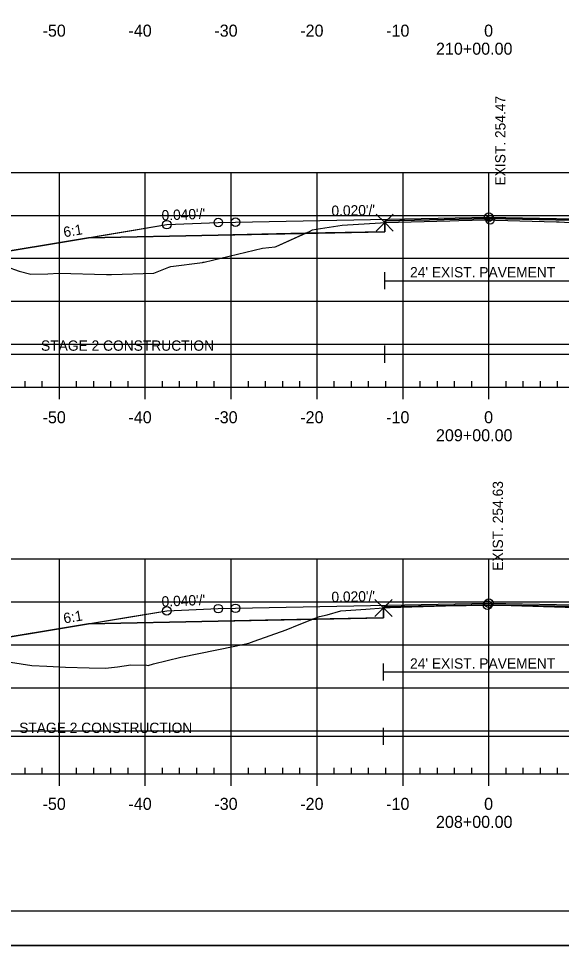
# Model space of a CAD drawing. Extents: x 1365647 to 1367999, y 387113 to 400173.
# Drawn here: x 1365839.3 to 1365902.5, y 390359.5 to 390467.4 of the extents above; entities that cross this region are included whole.
import ezdxf

# ---------------------------------------------------------------- set-up
doc = ezdxf.new("R2010")
doc.units = 0
for name, color, linetype in [('R_Alt Surface', 7, 'Continuous'), ('R_Axis', 7, 'Continuous'), ('R_Axis Annot', 7, 'Continuous'), ('R_Border', 7, 'Continuous'), ('R_Contours', 7, 'Continuous'), ('R_Exist Surface', 7, 'Continuous'), ('R_Fin Surface', 7, 'Continuous'), ('R_Fin Surface Annot', 7, 'Continuous'), ('R_Grid', 7, 'Continuous'), ('R_No Plot', 7, 'Continuous'), ('R_Water', 7, 'Continuous'), ('R_Xsect Elev', 7, 'Continuous')]:
    doc.layers.add(name, color=color, linetype=linetype)

msp = doc.modelspace()

# ---------------------------------------------------------------- linework, layer by layer
at = {"layer": 'R_Alt Surface'}
for points in [[(1365847.47, 390441.85), (1365862.59, 390442.16), (1365881.96, 390442.54), (1365881.96, 390443.83), (1365894.09, 390444.07), (1365905.79, 390443.84), (1365905.79, 390442.55), (1365925.59, 390442.16), (1365940.72, 390441.85)], [(1365847.47, 390396.91), (1365862.59, 390397.21), (1365881.82, 390397.59), (1365881.82, 390398.88), (1365894.09, 390399.13), (1365905.66, 390398.89), (1365905.66, 390397.61), (1365925.59, 390397.21), (1365940.72, 390396.91)]]:
    msp.add_lwpolyline(points, dxfattribs=at)
at = {"layer": 'R_Axis'}
for p, q in [((1365840.09, 390424.45), (1365840.09, 390425.15)), ((1365842.09, 390424.45), (1365842.09, 390425.15)), ((1365846.09, 390424.45), (1365846.09, 390425.15)), ((1365848.09, 390424.45), (1365848.09, 390425.15)), ((1365850.09, 390424.45), (1365850.09, 390425.15)), ((1365852.09, 390424.45), (1365852.09, 390425.15)), ((1365856.09, 390424.45), (1365856.09, 390425.15)), ((1365858.09, 390424.45), (1365858.09, 390425.15)), ((1365860.09, 390424.45), (1365860.09, 390425.15)), ((1365862.09, 390424.45), (1365862.09, 390425.15)), ((1365866.09, 390424.45), (1365866.09, 390425.15)), ((1365868.09, 390424.45), (1365868.09, 390425.15)), ((1365870.09, 390424.45), (1365870.09, 390425.15)), ((1365872.09, 390424.45), (1365872.09, 390425.15)), ((1365876.09, 390424.45), (1365876.09, 390425.15)), ((1365878.09, 390424.45), (1365878.09, 390425.15)), ((1365880.09, 390424.45), (1365880.09, 390425.15)), ((1365882.09, 390424.45), (1365882.09, 390425.15)), ((1365886.09, 390424.45), (1365886.09, 390425.15)), ((1365888.09, 390424.45), (1365888.09, 390425.15)), ((1365890.09, 390424.45), (1365890.09, 390425.15)), ((1365892.09, 390424.45), (1365892.09, 390425.15)), ((1365896.09, 390424.45), (1365896.09, 390425.15)), ((1365898.09, 390424.45), (1365898.09, 390425.15)), ((1365900.09, 390424.45), (1365900.09, 390425.15)), ((1365902.09, 390424.45), (1365902.09, 390425.15)), ((1365749.09, 390424.45), (1366039.09, 390424.45)), ((1365844.09, 390423.05), (1365844.09, 390424.45)), ((1365854.09, 390423.05), (1365854.09, 390424.45)), ((1365864.09, 390423.05), (1365864.09, 390424.45)), ((1365874.09, 390423.05), (1365874.09, 390424.45)), ((1365884.09, 390423.05), (1365884.09, 390424.45)), ((1365894.09, 390423.05), (1365894.09, 390424.45)), ((1365840.09, 390379.45), (1365840.09, 390380.15)), ((1365842.09, 390379.45), (1365842.09, 390380.15)), ((1365846.09, 390379.45), (1365846.09, 390380.15)), ((1365848.09, 390379.45), (1365848.09, 390380.15)), ((1365850.09, 390379.45), (1365850.09, 390380.15)), ((1365852.09, 390379.45), (1365852.09, 390380.15)), ((1365856.09, 390379.45), (1365856.09, 390380.15)), ((1365858.09, 390379.45), (1365858.09, 390380.15)), ((1365860.09, 390379.45), (1365860.09, 390380.15)), ((1365862.09, 390379.45), (1365862.09, 390380.15)), ((1365866.09, 390379.45), (1365866.09, 390380.15)), ((1365868.09, 390379.45), (1365868.09, 390380.15)), ((1365870.09, 390379.45), (1365870.09, 390380.15)), ((1365872.09, 390379.45), (1365872.09, 390380.15)), ((1365876.09, 390379.45), (1365876.09, 390380.15)), ((1365878.09, 390379.45), (1365878.09, 390380.15)), ((1365880.09, 390379.45), (1365880.09, 390380.15)), ((1365882.09, 390379.45), (1365882.09, 390380.15)), ((1365886.09, 390379.45), (1365886.09, 390380.15)), ((1365888.09, 390379.45), (1365888.09, 390380.15)), ((1365890.09, 390379.45), (1365890.09, 390380.15)), ((1365892.09, 390379.45), (1365892.09, 390380.15)), ((1365896.09, 390379.45), (1365896.09, 390380.15)), ((1365898.09, 390379.45), (1365898.09, 390380.15)), ((1365900.09, 390379.45), (1365900.09, 390380.15)), ((1365902.09, 390379.45), (1365902.09, 390380.15)), ((1365749.09, 390379.45), (1366039.09, 390379.45)), ((1365844.09, 390378.05), (1365844.09, 390379.45)), ((1365854.09, 390378.05), (1365854.09, 390379.45)), ((1365864.09, 390378.05), (1365864.09, 390379.45)), ((1365874.09, 390378.05), (1365874.09, 390379.45)), ((1365884.09, 390378.05), (1365884.09, 390379.45)), ((1365894.09, 390378.05), (1365894.09, 390379.45))]:
    msp.add_line(p, q, dxfattribs=at)
at = {"layer": 'R_Border'}
msp.add_line((1366052.27, 390363.45), (1365736.09, 390363.45), dxfattribs=at)
at = {"layer": 'R_Contours'}
for points in [[(1365872.75, 390442.36), (1365873.19, 390442.56), (1365873.55, 390442.75), (1365873.99, 390442.83), (1365877, 390443.32), (1365881.48, 390443.57), (1365881.96, 390443.6), (1365881.96, 390442.54)], [(1365881.96, 390443.6), (1365882.07, 390443.61), (1365889.54, 390443.83), (1365890.57, 390443.86), (1365893.74, 390443.92), (1365894.07, 390443.92), (1365894.22, 390443.92), (1365894.25, 390443.92), (1365894.87, 390443.9), (1365901.94, 390443.7), (1365902.25, 390443.69), (1365905.37, 390443.52), (1365905.79, 390443.5), (1365905.79, 390443.84), (1365894.09, 390444.07), (1365881.96, 390443.83)], [(1365832.89, 390439.14), (1365833.73, 390439.05), (1365835.07, 390438.94), (1365837.89, 390438.49), (1365839.41, 390437.96), (1365840.78, 390437.6), (1365842.75, 390437.66), (1365844.02, 390437.71), (1365849.58, 390437.55), (1365849.9, 390437.55), (1365850.15, 390437.55), (1365855.08, 390437.72), (1365856.82, 390438.41), (1365857.08, 390438.5), (1365860.75, 390438.98), (1365860.82, 390438.99), (1365860.93, 390439.01), (1365867.74, 390440.64), (1365869.19, 390440.8), (1365869.32, 390440.83), (1365872.75, 390442.36), (1365862.59, 390442.16), (1365847.47, 390441.85), (1365834.59, 390439.71)], [(1365873.55, 390397.43), (1365874.36, 390397.74), (1365875.25, 390397.96), (1365876.87, 390398.41), (1365879.78, 390398.6), (1365881.82, 390398.75), (1365881.82, 390397.59)], [(1365881.82, 390398.75), (1365882.38, 390398.79), (1365882.61, 390398.8), (1365883.85, 390398.84), (1365890.3, 390399.02), (1365891.43, 390399.03), (1365893.93, 390399.08), (1365894.26, 390399.09), (1365894.37, 390399.09), (1365895.4, 390399.07), (1365902.95, 390398.84), (1365903.63, 390398.82), (1365904.3, 390398.78), (1365905.66, 390398.71), (1365905.66, 390398.89), (1365894.09, 390399.13), (1365881.82, 390398.88)]]:
    msp.add_lwpolyline(points, close=True, dxfattribs=at)
msp.add_lwpolyline([(1365835.87, 390392.84), (1365840.87, 390392.06), (1365842.61, 390391.99), (1365844.81, 390391.87), (1365847.55, 390391.8), (1365849.47, 390391.75), (1365850.85, 390391.91), (1365852.42, 390392.15), (1365854.26, 390392.09), (1365854.43, 390392.07), (1365855.05, 390392.23), (1365858.23, 390393.01), (1365864.53, 390394.3), (1365866.15, 390394.65), (1365866.76, 390394.87), (1365870.5, 390396.22), (1365872, 390396.83), (1365873.55, 390397.43), (1365862.59, 390397.21), (1365847.47, 390396.91), (1365834.59, 390394.76)], dxfattribs=at)
at = {"layer": 'R_Exist Surface'}
for points in [[(1365837.89, 390438.49), (1365839.41, 390437.96), (1365840.78, 390437.6), (1365842.75, 390437.66), (1365844.02, 390437.71), (1365849.58, 390437.55), (1365849.9, 390437.55), (1365850.15, 390437.55), (1365855.08, 390437.72), (1365856.82, 390438.41), (1365857.08, 390438.5), (1365860.75, 390438.98), (1365860.82, 390438.99), (1365860.93, 390439.01), (1365867.74, 390440.64), (1365869.19, 390440.8), (1365869.32, 390440.83), (1365873.19, 390442.56), (1365873.55, 390442.75), (1365873.99, 390442.83), (1365877, 390443.32), (1365881.48, 390443.57), (1365881.96, 390443.6), (1365882.07, 390443.61), (1365889.54, 390443.83), (1365890.57, 390443.86), (1365893.74, 390443.92), (1365894.07, 390443.92), (1365894.22, 390443.92), (1365894.25, 390443.92), (1365894.87, 390443.9), (1365901.94, 390443.7), (1365902.25, 390443.69), (1365905.37, 390443.52)], [(1365835.87, 390392.84), (1365840.87, 390392.06), (1365842.61, 390391.99), (1365844.81, 390391.87), (1365847.55, 390391.8), (1365849.47, 390391.75), (1365850.85, 390391.91), (1365852.42, 390392.15), (1365854.26, 390392.09), (1365854.43, 390392.07), (1365855.05, 390392.23), (1365858.23, 390393.01), (1365864.53, 390394.3), (1365866.15, 390394.65), (1365866.76, 390394.87), (1365870.5, 390396.22), (1365872, 390396.83), (1365874.36, 390397.74), (1365875.25, 390397.96), (1365876.87, 390398.41), (1365879.78, 390398.6), (1365881.82, 390398.75), (1365882.38, 390398.79), (1365882.61, 390398.8), (1365883.85, 390398.84), (1365890.3, 390399.02), (1365891.43, 390399.03), (1365893.93, 390399.08), (1365894.26, 390399.09), (1365894.37, 390399.09), (1365895.4, 390399.07), (1365902.95, 390398.84)]]:
    msp.add_lwpolyline(points, dxfattribs=at)
at = {"layer": 'R_Fin Surface'}
for points in [[(1365823.17, 390439), (1365827.81, 390437.45), (1365834.59, 390439.71), (1365847.47, 390441.85), (1365856.59, 390443.37), (1365862.59, 390443.61), (1365864.59, 390443.65), (1365894.09, 390444.24), (1365923.59, 390443.65), (1365925.59, 390443.61), (1365931.59, 390443.37), (1365940.72, 390441.85), (1365953.59, 390439.71), (1365961.09, 390437.21), (1365964.15, 390438.23)], [(1365829.91, 390438.15), (1365834.59, 390439.71), (1365856.59, 390443.37), (1365862.59, 390443.61), (1365864.59, 390443.65), (1365894.09, 390444.24), (1365923.59, 390443.65), (1365925.59, 390443.61), (1365931.59, 390443.37), (1365953.59, 390439.71), (1365961.09, 390437.21), (1365964.15, 390438.23)], [(1365832.89, 390439.14), (1365834.59, 390439.71), (1365852.3, 390442.66), (1365856.59, 390443.37), (1365862.59, 390443.61), (1365864.59, 390443.65), (1365894.09, 390444.24), (1365923.59, 390443.65), (1365925.59, 390443.61), (1365931.59, 390443.37), (1365935.89, 390442.66), (1365953.59, 390439.71)], [(1365856.59, 390443.37), (1365862.59, 390443.61), (1365864.59, 390443.65), (1365894.09, 390444.24), (1365923.59, 390443.65), (1365925.59, 390443.61), (1365931.59, 390443.37)], [(1365818.9, 390393.37), (1365824.66, 390391.45), (1365834.59, 390394.76), (1365847.47, 390396.91), (1365856.59, 390398.43), (1365862.59, 390398.67), (1365864.59, 390398.71), (1365894.09, 390399.3), (1365923.59, 390398.71), (1365925.59, 390398.67), (1365931.59, 390398.43), (1365940.72, 390396.91), (1365953.59, 390394.76), (1365962.39, 390391.83), (1365965.77, 390392.95)], [(1365827.66, 390392.45), (1365834.59, 390394.76), (1365856.59, 390398.43), (1365862.59, 390398.67), (1365864.59, 390398.71), (1365894.09, 390399.3), (1365923.59, 390398.71), (1365925.59, 390398.67), (1365931.59, 390398.43), (1365953.59, 390394.76), (1365962.39, 390391.83), (1365965.77, 390392.95)], [(1365829.97, 390393.22), (1365834.59, 390394.76), (1365852.3, 390397.71), (1365856.59, 390398.43), (1365862.59, 390398.67), (1365864.59, 390398.71), (1365894.09, 390399.3), (1365923.59, 390398.71), (1365925.59, 390398.67), (1365931.59, 390398.43), (1365935.89, 390397.71), (1365953.59, 390394.76), (1365959.02, 390392.95)], [(1365856.59, 390398.43), (1365862.59, 390398.67), (1365864.59, 390398.71), (1365894.09, 390399.3), (1365923.59, 390398.71), (1365925.59, 390398.67), (1365931.59, 390398.43)]]:
    msp.add_lwpolyline(points, dxfattribs=at)
at = {"layer": 'R_Grid'}
for p, q in [((1365749.09, 390449.45), (1366039.09, 390449.45)), ((1365844.09, 390424.45), (1365844.09, 390449.45)), ((1365854.09, 390424.45), (1365854.09, 390449.45)), ((1365864.09, 390424.45), (1365864.09, 390449.45)), ((1365874.09, 390424.45), (1365874.09, 390449.45)), ((1365884.09, 390424.45), (1365884.09, 390449.45)), ((1365894.09, 390424.45), (1365894.09, 390449.45)), ((1365749.09, 390444.45), (1366039.09, 390444.45)), ((1365749.09, 390439.45), (1366039.09, 390439.45)), ((1365749.09, 390434.45), (1366039.09, 390434.45)), ((1365749.09, 390429.45), (1366039.09, 390429.45)), ((1365749.09, 390424.45), (1366039.09, 390424.45)), ((1365749.09, 390404.45), (1366039.09, 390404.45)), ((1365844.09, 390379.45), (1365844.09, 390404.45)), ((1365854.09, 390379.45), (1365854.09, 390404.45)), ((1365864.09, 390379.45), (1365864.09, 390404.45)), ((1365874.09, 390379.45), (1365874.09, 390404.45)), ((1365884.09, 390379.45), (1365884.09, 390404.45)), ((1365894.09, 390379.45), (1365894.09, 390404.45)), ((1365749.09, 390399.45), (1366039.09, 390399.45)), ((1365749.09, 390394.45), (1366039.09, 390394.45)), ((1365749.09, 390389.45), (1366039.09, 390389.45)), ((1365749.09, 390384.45), (1366039.09, 390384.45)), ((1365749.09, 390379.45), (1366039.09, 390379.45))]:
    msp.add_line(p, q, dxfattribs=at)
at = {"layer": 'R_No Plot'}
msp.add_line((1365723.69, 390359.47), (1366057.03, 390359.47), dxfattribs=at)
msp.add_lwpolyline([(1365723.69, 390572.8), (1366057.03, 390572.8), (1366057.03, 390359.47), (1365723.69, 390359.47)], close=True, dxfattribs=at)
for points in [[(1365881.96, 390443.6), (1365880.96, 390444.6), (1365881.96, 390443.6), (1365880.96, 390442.6), (1365881.96, 390443.6), (1365882.96, 390442.6), (1365881.96, 390443.6), (1365882.96, 390444.6)], [(1365881.82, 390398.75), (1365880.82, 390399.75), (1365881.82, 390398.75), (1365880.82, 390397.75), (1365881.82, 390398.75), (1365882.82, 390397.75), (1365881.82, 390398.75), (1365882.82, 390399.75)]]:
    msp.add_lwpolyline(points, dxfattribs=at)
for centre in [(1365894.09, 390444.24), (1365894.09, 390444.24), (1365894.09, 390444.24), (1365894.09, 390444.24), (1365894.09, 390444.24), (1365856.59, 390443.37), (1365856.59, 390443.37), (1365856.59, 390443.37), (1365856.59, 390443.37), (1365856.59, 390443.37), (1365862.59, 390443.61), (1365862.59, 390443.61), (1365862.59, 390443.61), (1365862.59, 390443.61), (1365862.59, 390443.61), (1365864.59, 390443.65), (1365864.59, 390443.65), (1365864.59, 390443.65), (1365864.59, 390443.65), (1365864.59, 390443.65), (1365894.22, 390443.92), (1365893.93, 390399.08), (1365894.09, 390399.3), (1365894.09, 390399.3), (1365894.09, 390399.3), (1365894.09, 390399.3), (1365894.09, 390399.3), (1365856.59, 390398.43), (1365856.59, 390398.43), (1365856.59, 390398.43), (1365856.59, 390398.43), (1365856.59, 390398.43), (1365862.59, 390398.67), (1365862.59, 390398.67), (1365862.59, 390398.67), (1365862.59, 390398.67), (1365862.59, 390398.67), (1365864.59, 390398.71), (1365864.59, 390398.71), (1365864.59, 390398.71), (1365864.59, 390398.71), (1365864.59, 390398.71)]:
    msp.add_circle(centre, 0.5, dxfattribs=at)
at = {"layer": 'R_Water'}
for p, q in [((1365881.96, 390435.84), (1365881.96, 390437.84)), ((1365881.96, 390436.84), (1365905.79, 390436.84)), ((1365881.96, 390427.3), (1365881.96, 390429.3)), ((1365823.17, 390428.3), (1365881.96, 390428.3)), ((1365881.96, 390428.3), (1365964.15, 390428.3)), ((1365881.82, 390390.3), (1365881.82, 390392.3)), ((1365881.82, 390391.3), (1365905.66, 390391.3)), ((1365881.82, 390382.81), (1365881.82, 390384.81)), ((1365818.9, 390383.81), (1365881.82, 390383.81)), ((1365881.82, 390383.81), (1365965.77, 390383.81))]:
    msp.add_line(p, q, dxfattribs=at)

# ---------------------------------------------------------------- texts
at = {"layer": 'R_Axis Annot'}
for s, p in [('-50', (1365842.13, 390465.25)), ('-40', (1365852.13, 390465.25)), ('-30', (1365862.13, 390465.25)), ('-20', (1365872.13, 390465.25)), ('-10', (1365882.13, 390465.25)), ('0', (1365893.53, 390465.25)), ('210+00.00', (1365887.93, 390463.15)), ('-50', (1365842.13, 390420.25)), ('-40', (1365852.13, 390420.25)), ('-30', (1365862.13, 390420.25)), ('-20', (1365872.13, 390420.25)), ('-10', (1365882.13, 390420.25)), ('0', (1365893.53, 390420.25)), ('209+00.00', (1365887.93, 390418.15)), ('-50', (1365842.13, 390375.25)), ('-40', (1365852.13, 390375.25)), ('-30', (1365862.13, 390375.25)), ('-20', (1365872.13, 390375.25)), ('-10', (1365882.13, 390375.25)), ('0', (1365893.53, 390375.25)), ('208+00.00', (1365887.93, 390373.15))]:
    msp.add_text(s, height=1.4, dxfattribs=at).set_placement(p)
at = {"layer": 'R_Fin Surface Annot'}
for s, rotation, p in [("0.020'/'", 1.1458, (1365875.77, 390444.38)), ("0.040'/'", 2.2906, (1365856.01, 390443.85)), ('6:1', 9.4623, (1365844.66, 390441.89)), ("0.040'/'", 2.2906, (1365856.01, 390398.9)), ("0.020'/'", 1.1458, (1365875.77, 390399.43)), ('6:1', 9.4623, (1365844.66, 390396.94))]:
    msp.add_text(s, height=1.2, rotation=rotation, dxfattribs=at).set_placement(p)
at = {"layer": 'R_Water'}
for s, p in [("24' EXIST. PAVEMENT", (1365884.91, 390437.23)), ('STAGE 2 CONSTRUCTION', (1365841.95, 390428.69)), ("24' EXIST. PAVEMENT", (1365884.91, 390391.69)), ('STAGE 2 CONSTRUCTION', (1365839.41, 390384.2))]:
    msp.add_text(s, height=1.2, dxfattribs=at).set_placement(p)
at = {"layer": 'R_Xsect Elev'}
for s, p in [('EXIST. 254.47', (1365896.02, 390447.92)), ('EXIST. 254.63', (1365895.73, 390403.08))]:
    msp.add_text(s, height=1.2, rotation=90, dxfattribs=at).set_placement(p)

doc.saveas('drawing.dxf')
